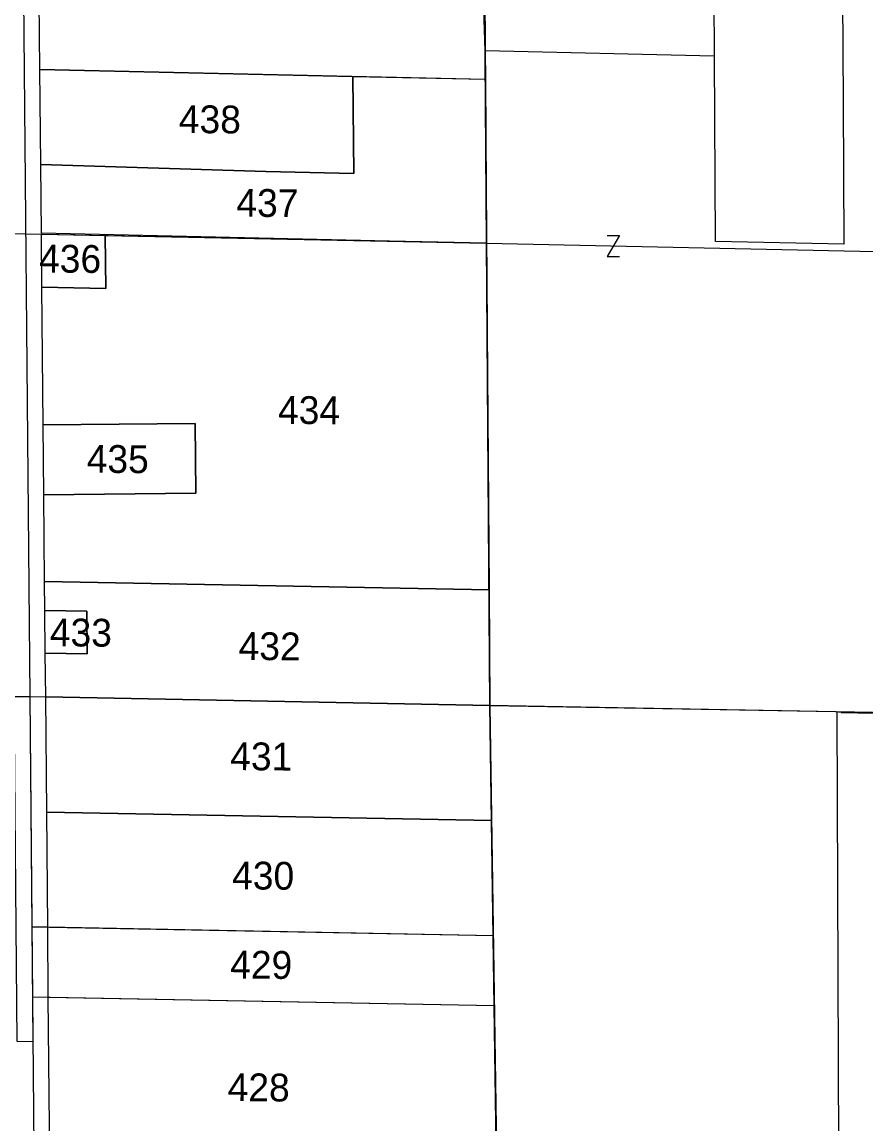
# Model space of a CAD drawing. Extents: x 582596 to 627039, y 145946 to 197316.
# Drawn here: x 604584 to 607001, y 171651 to 174808 of the extents above; entities that cross this region are included whole.
import ezdxf

# ---------------------------------------------------------------- set-up
doc = ezdxf.new("R2010")
doc.units = 0
for name, color, linetype in [('Defpoints 2', 7, 'Continuous'), ('E_RW_Existing', 7, 'Continuous'), ('E_RW_SixteenthLine', 7, 'Continuous'), ('P_MISC_NoPlot', 7, 'Continuous'), ('P_RW_PropertyConnector', 7, 'Continuous'), ('P_RW_PropertyLine', 7, 'Continuous'), ('P_RW_QuarterLine', 7, 'Continuous'), ('P_RW_SectionLine', 7, 'Continuous')]:
    doc.layers.add(name, color=color, linetype=linetype)

msp = doc.modelspace()

# ---------------------------------------------------------------- linework, layer by layer
at = {"layer": 'E_RW_Existing'}
for points in [[(604606.3, 172875.4), (604614.9, 171886.7), (604569.8, 171887.4), (604561.3, 172876)], [(604612, 172215.4), (604613.7, 172015.4), (604658.8, 172014.6), (604657, 172214.5)]]:
    msp.add_lwpolyline(points, close=True, dxfattribs=at)
at = {"layer": 'E_RW_SixteenthLine'}
for p, q in [((605904.6, 175497.2), (605923.5, 172850.3)), ((601935, 174239.7), (604594.1, 174201.1)), ((604594.1, 174201.1), (605914.1, 174173.8)), ((605914.1, 174173.8), (607234, 174146.4)), ((605923.5, 172850.3), (605943, 171523.9))]:
    msp.add_line(p, q, dxfattribs=at)
at = {"layer": 'P_MISC_NoPlot'}
for points in [[(606993.6, 160308.3), (600102.2, 147849.8), (582596.4, 147849.8), (584141, 197316), (605971.8, 196079.3), (609781.9, 181857.8), (607212.6, 178117.5), (605887.7, 178149.4), (605896.2, 176823.3), (605904.6, 175497.2), (605914.1, 174173.8), (605923.5, 172850.3), (605943, 171523.9), (604673.2, 170334), (604629.1, 170230.1), (604629.4, 170060), (605962, 170045), (605958.9, 168865.5), (605954.8, 167533.5), (604633.8, 167557.8), (604638.5, 164918.1), (606975.2, 164878.2), (606986.2, 162297)], [(606993.6, 160308.3), (600102.2, 147849.8), (582596.4, 147849.8), (584141, 197316), (605971.8, 196079.3), (609781.9, 181857.8), (607212.6, 178117.5), (605887.7, 178149.4), (605896.2, 176823.3), (605904.6, 175497.2), (605914.1, 174173.8), (605923.5, 172850.3), (605943, 171523.9), (604673.2, 170334), (604629.1, 170230.1), (604629.4, 170060), (605962, 170045), (605958.9, 168865.5), (605954.8, 167533.5), (604633.8, 167557.8), (604638.5, 164918.1), (606975.2, 164878.2), (606986.2, 162297)], [(606993.6, 160308.3), (600102.2, 147849.8), (582596.4, 147849.8), (584141, 197316), (605971.8, 196079.3), (609781.9, 181857.8), (607212.6, 178117.5), (605887.7, 178149.4), (605896.2, 176823.3), (605904.6, 175497.2), (605914.1, 174173.8), (605923.5, 172850.3), (605943, 171523.9), (604673.2, 170334), (604629.1, 170230.1), (604629.4, 170060), (605962, 170045), (605958.9, 168865.5), (605954.8, 167533.5), (604633.8, 167557.8), (604638.5, 164918.1), (606975.2, 164878.2), (606986.2, 162297)], [(606996.1, 159645.4), (606986.2, 162297), (606975.2, 164878.2), (604638.5, 164918.1), (604633.8, 167557.8), (605954.8, 167533.5), (605962, 170045), (604629.4, 170060), (604629.1, 170230.1), (604673.2, 170334), (605943, 171523.9), (605923.5, 172850.3), (605914.1, 174173.8), (605904.6, 175497.2), (605896.2, 176823.3), (605887.7, 178149.4), (607212.6, 178117.5), (607212.6, 178117.5), (627039.4, 170600.9), (626501.4, 158385.8), (609890.9, 158385.8), (607772.6, 159126.1)]]:
    msp.add_lwpolyline(points, close=True, dxfattribs=at)
at = {"layer": 'P_RW_PropertyConnector'}
for p, q in [((606259.3, 174196.2), (606294.9, 174196.2)), ((606294.9, 174196.2), (606259.3, 174136.2)), ((606277.1, 174166.2), (606277.1, 174166.2)), ((606259.3, 174136.2), (606294.9, 174136.2))]:
    msp.add_line(p, q, dxfattribs=at)
at = {"layer": 'P_RW_PropertyLine'}
for p, q in [((606562.7, 175449.4), (606566.4, 174710)), ((606933.1, 175053), (606935.6, 174578)), ((606566.4, 174710), (605910.1, 174724.7)), ((605910.1, 174724.7), (605910.7, 174642.8)), ((606567, 174708.7), (606567, 174708.9)), ((606567, 174708.9), (606567, 174708.7)), ((606569.8, 174179.2), (606567, 174708.7)), ((606935.6, 174578), (606937.7, 174171)), ((606937.7, 174171), (606569.8, 174179.2)), ((606913.7, 172831.5), (605923.5, 172848.9)), ((606929.6, 172829.8), (606913.7, 172831.5)), ((606923.9, 171502.6), (606918.3, 172831.4)), ((606929.6, 172829.8), (607074.5, 172827.1)), ((607074.5, 172827.1), (606929.6, 172829.8))]:
    msp.add_line(p, q, dxfattribs=at)
for points in [[(605910.1, 174724.7), (605895.2, 175208.6), (605905, 175437.2), (605905, 175437.2), (605904.8, 175464.2), (605904.9, 175464.2)], [(605910.7, 174642.8), (604634.8, 174671.5), (604632, 174970.2), (604647, 174970.3), (604643.2, 175385.6), (604682.7, 175424.6), (605014.6, 175417.2), (605735.3, 175440.7), (605730.3, 175212.3), (605895.2, 175208.6), (605910.1, 174724.7), (605910.7, 174642.8)], [(605910.1, 174724.7), (605923.5, 172850.3)], [(605914.1, 174173.8), (605636.4, 174179.5), (604639.1, 174203.1), (604637.3, 174399.3), (605282.3, 174379.5), (605533.7, 174374), (605531.1, 174651.9), (605910.7, 174643.6)], [(605910.7, 174643.6), (605914.1, 174173.8)], [(605921.1, 173181), (604648.3, 173205.2), (604646, 173453.6), (605081, 173457.6), (605079.2, 173657.6), (604644.2, 173653.6), (604640.5, 174048.3), (604823.4, 174044.5), (604822.1, 174196.4), (605914.1, 174173.8)], [(605914.1, 174173.8), (605921.1, 173181)], [(605928.3, 172520.3), (604654.2, 172544.5), (604651.4, 172874.5), (605923.5, 172850.3)], [(605923.5, 172850.3), (605928.3, 172520.3)], [(605943, 171523.9), (604662.7, 171551.8), (604658.8, 172014.6), (605936.1, 171990.3), (605943, 171523.9)]]:
    msp.add_lwpolyline(points, dxfattribs=at)
for points in [[(604634.8, 174671.6), (605531.1, 174651.9), (605533.7, 174374), (605282.3, 174379.5), (604637.3, 174399.3)], [(604640.5, 174048.3), (604639.1, 174200.2), (604822.1, 174196.4), (604823.4, 174044.5)], [(604644.2, 173653.6), (605079.2, 173657.6), (605081, 173457.6), (604646, 173453.6)], [(604651.4, 172874.5), (604650.2, 173000.2), (604770.2, 172998), (604769.1, 173119.9), (604649.1, 173122.2), (604648.3, 173205.2), (605921.1, 173181), (605923.5, 172850.3)], [(604649.1, 173122.2), (604769.1, 173119.9), (604770.2, 172998), (604650.2, 173000.2)], [(604654.2, 172544.5), (605928.3, 172520.3), (605933.2, 172190.3), (604657, 172214.5)], [(605936.1, 171990.3), (605933.2, 172190.3), (604612, 172215.4), (604613.7, 172015.4)]]:
    msp.add_lwpolyline(points, close=True, dxfattribs=at)
at = {"layer": 'P_RW_QuarterLine'}
msp.add_line((607240.6, 172825.3), (605923.5, 172850.3), dxfattribs=at)
at = {"layer": 'P_RW_SectionLine'}
for p, q in [((604581.9, 175526.9), (604606.3, 172875.4)), ((601947.1, 172912.5), (604606.3, 172875.4)), ((604606.3, 172875.4), (605923.5, 172850.3)), ((604606.3, 172875.4), (604629.1, 170230.1))]:
    msp.add_line(p, q, dxfattribs=at)

# ---------------------------------------------------------------- texts
at = {"layer": 'Defpoints 2'}
for s, p in [('438', (605032.4, 174489.8)), ('437', (605197.2, 174250.1)), ('436', (604632.1, 174090.3)), ('434', (605316.5, 173656.8)), ('435', (604768.5, 173516.7)), ('433', (604662.9, 173019.7)), ('432', (605203.7, 172980.6)), ('431', (605179.6, 172665)), ('430', (605185, 172323.5)), ('429', (605179.4, 172068.1)), ('428', (605172.2, 171717))]:
    msp.add_text(s, height=79.68, rotation=359.5042, dxfattribs=at).set_placement(p)

doc.saveas('drawing.dxf')
